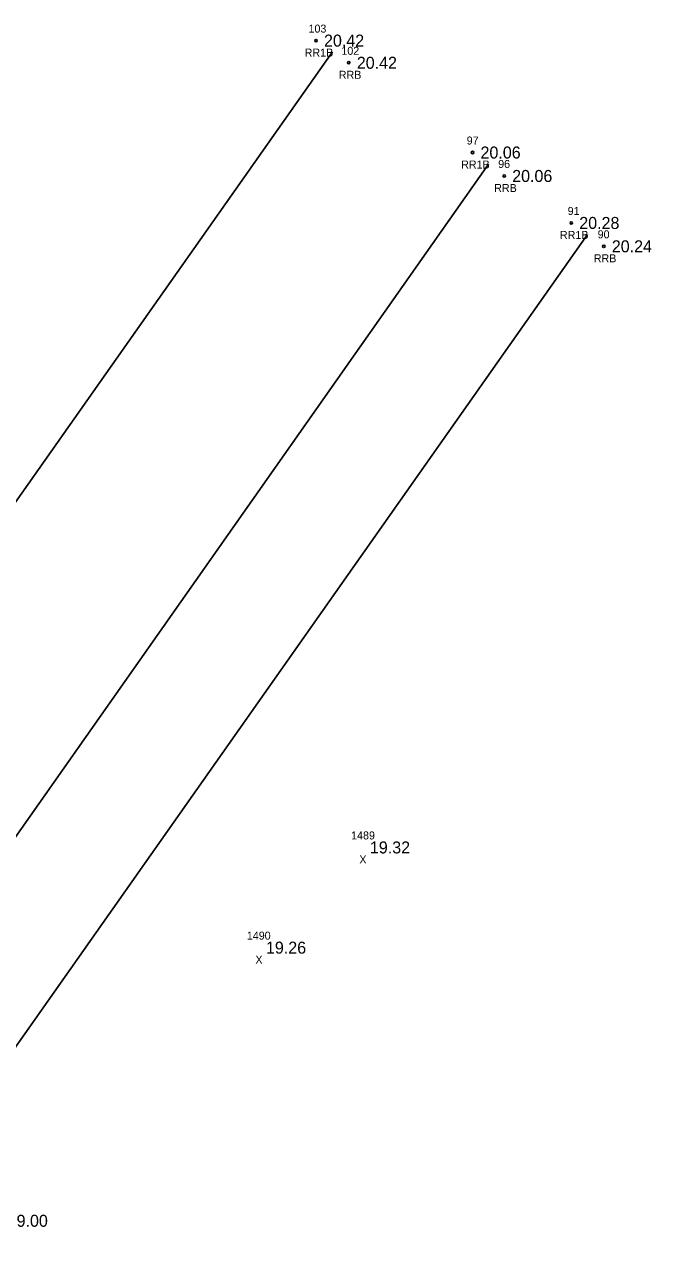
# Model space of a CAD drawing. Extents: x 2042117 to 2045853, y 303080 to 309569.
# Drawn here: x 2043538.3 to 2043616.7, y 305904.8 to 306057.8 of the extents above; entities that cross this region are included whole.
import ezdxf

# ---------------------------------------------------------------- set-up
doc = ezdxf.new("R2010")
doc.units = 0
for name, color, linetype in [('RD_EX_Misc_txCode', 7, 'Continuous'), ('RD_EX_RailRoad', 7, 'Continuous'), ('RD_EX_RailRoad_txCode', 7, 'Continuous'), ('RD_EX_TX_Misc_ELEV', 7, 'Continuous'), ('RD_EX_TX_RailRoad_ELEV', 7, 'Continuous'), ('RD_SMD_Locator', 7, 'Continuous')]:
    doc.layers.add(name, color=color, linetype=linetype)

msp = doc.modelspace()

# ---------------------------------------------------------------- linework, layer by layer
at = {"layer": 'RD_EX_RailRoad'}
for points in [[(2043319.01, 305688.39), (2043467.58, 305899.4), (2043576.81, 306054.41)], [(2043364.31, 305710.83), (2043487.58, 305885.88), (2043596.31, 306040.36)], [(2043376.84, 305702.3), (2043499.95, 305877.29), (2043608.72, 306031.56)]]:
    msp.add_lwpolyline(points, dxfattribs=at)
at = {"layer": 'RD_SMD_Locator'}
for centre in [(2043574.76, 306055.8), (2043578.86, 306053.03), (2043594.33, 306041.82), (2043598.29, 306038.89), (2043606.68, 306033.02), (2043610.75, 306030.1)]:
    msp.add_circle(centre, 0.15, dxfattribs=at)

# ---------------------------------------------------------------- texts
at = {"layer": 'RD_EX_Misc_txCode'}
for s, p in [('1489', (2043579.15, 305956)), ('X', (2043580.18, 305953)), ('1490', (2043566.11, 305943.48)), ('X', (2043567.18, 305940.48))]:
    msp.add_text(s, height=1, dxfattribs=at).set_placement(p)
at = {"layer": 'RD_EX_RailRoad_txCode'}
for s, p in [('103', (2043573.82, 306056.8)), ('RR1B', (2043573.34, 306053.8)), ('102', (2043577.93, 306054.03)), ('RRB', (2043577.61, 306051.03)), ('97', (2043593.6, 306042.82)), ('96', (2043597.54, 306039.89)), ('RR1B', (2043592.91, 306039.82)), ('RRB', (2043597.04, 306036.89)), ('91', (2043606.23, 306034.02)), ('RR1B', (2043605.26, 306031.02)), ('90', (2043609.98, 306031.1)), ('RRB', (2043609.5, 306028.1))]:
    msp.add_text(s, height=1, dxfattribs=at).set_placement(p)
at = {"layer": 'RD_EX_TX_Misc_ELEV'}
for s, p in [('19.32', (2043581.5, 305954.25)), ('19.26', (2043568.5, 305941.73)), ('19.00', (2043536.2, 305907.61))]:
    msp.add_text(s, height=1.5, dxfattribs=at).set_placement(p)
at = {"layer": 'RD_EX_TX_RailRoad_ELEV'}
for s, p in [('20.42', (2043575.76, 306055.05)), ('20.42', (2043579.86, 306052.28)), ('20.06', (2043595.33, 306041.07)), ('20.06', (2043599.29, 306038.14)), ('20.28', (2043607.68, 306032.27)), ('20.24', (2043611.75, 306029.35))]:
    msp.add_text(s, height=1.5, dxfattribs=at).set_placement(p)

doc.saveas('drawing.dxf')
